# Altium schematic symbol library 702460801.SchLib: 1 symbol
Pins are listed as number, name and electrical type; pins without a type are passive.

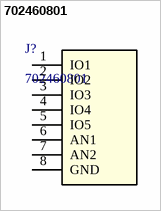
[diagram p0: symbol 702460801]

## 702460801
designator J?
2.54mm Pitch C-Grid Header, Low Profile, Dual Row, Vertical, Shrouded, 8  Circuits, 0.38Âµm Gold (Au) Selective Plating; Manufacturer_Name: Molex Connector Corporation
footprint CONN_7024608xx_MOL
pins: 1 IO1, 2 IO2, 3 IO3, 4 IO4, 5 IO5, 6 AN1, 7 AN2, 8 GND (power)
